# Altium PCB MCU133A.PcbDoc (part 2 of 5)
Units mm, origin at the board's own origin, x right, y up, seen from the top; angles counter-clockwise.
Board outline 58.42 x 139.7 mm, 4 copper layers (Top Signal, GND, PWR, Bottom Signal), stack 1.565 mm thick; 278 components, 226 nets, 1057 pads, 868 vias.
Unrouted connection lines stored in the file: 237.
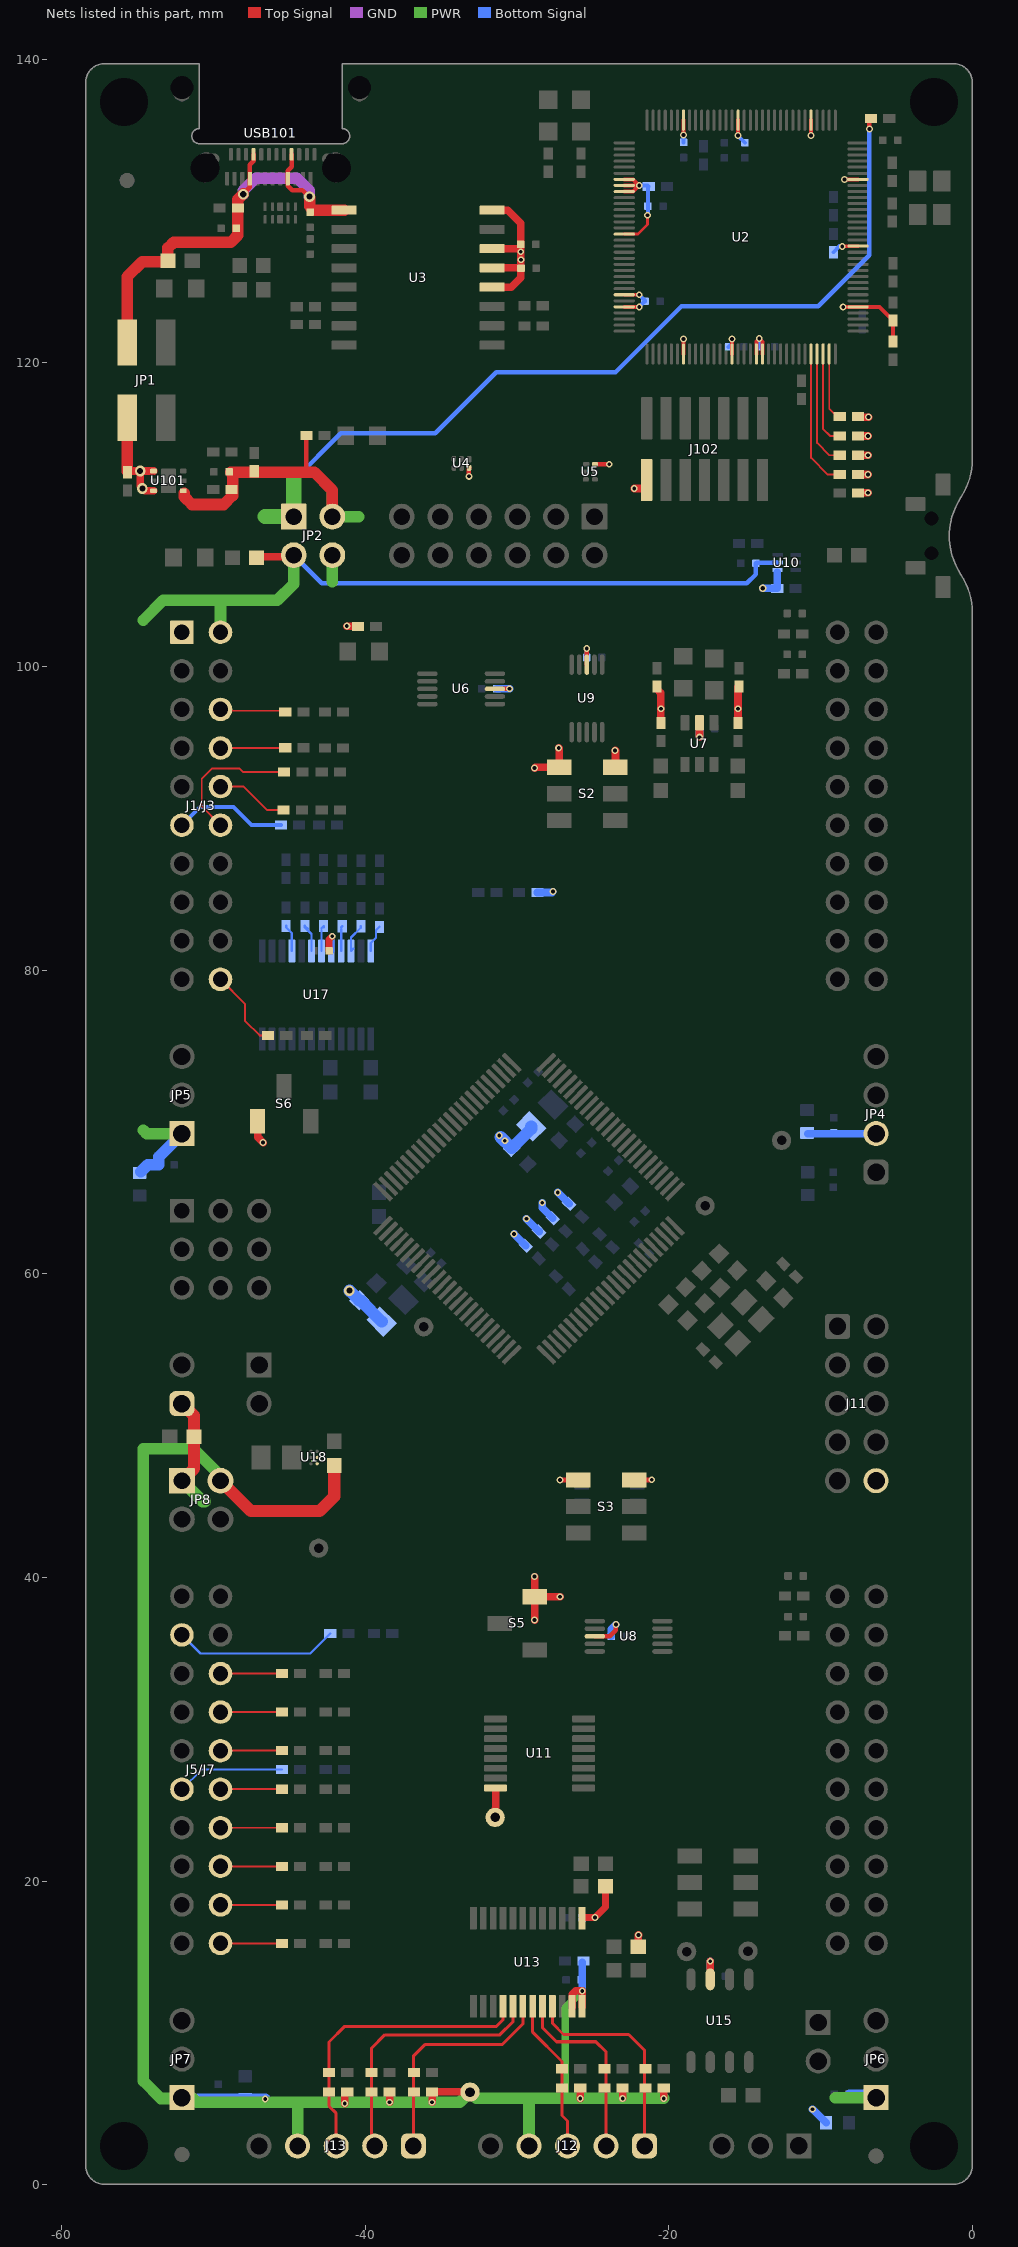
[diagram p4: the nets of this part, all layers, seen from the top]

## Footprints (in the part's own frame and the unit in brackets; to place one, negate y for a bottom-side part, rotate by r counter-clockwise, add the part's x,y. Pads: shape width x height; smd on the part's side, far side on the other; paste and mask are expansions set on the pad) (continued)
WURTH_61300211121#1 [mm] "Header, 2.54mm, 2x1, TH"
  rect 1.65x1.65 hole 1.15: 1(-1.27,0)
  round 1.65 hole 1.15: 2(1.27,0)
  silkscreen extent -2.54,-1.27 2.54,1.6, body extent -2.54,-1.27 2.54,1.27, height 8.54
WURTH_61300211121#2 [mm] "Header, 2.54mm, 2x1, TH"
  rrect50% 1.65x1.65 hole 1.15: 1(-1.27,0)
  round 1.65 hole 1.15: 2(1.27,0)
  body extent -2.54,-1.27 2.54,1.27, height 8.54
WURTH_61300311121 [mm] "Header, 2.54mm, 3x1, TH"
  rect 1.65x1.65 hole 1.15: 1(-2.54,0)
  round 1.65 hole 1.15: 2(0,0) 3(2.54,0)
  silkscreen extent -3.81,-1.65 3.81,1.27, body extent -3.81,-1.27 3.81,1.27, height 8.54
WURTH_61300411121 [mm] "Header, 2.54mm, 4x1, TH"
  rrect50% 1.65x1.65 hole 1.15: 1(-3.81,0)
  round 1.65 hole 1.15: 2(-1.27,0) 3(1.27,0) 4(3.81,0)
  body extent -5.08,-1.27 5.08,1.27, height 8.54
Wurth_61300511121 [mm] "Header, 2.54mm, 5x1, TH"
  rrect50% 1.65x1.65 hole 1.1: 1(-5.08,0)
  round 1.65 hole 1.1: 2(-2.54,0) 3(0,0) 4(2.54,0) 5(5.08,0)
  body extent -6.35,-1.27 6.35,1.27, height 8.54
WURTH_61301021121 [mm] "Header, 2.54mm, 5x2, TH"
  rrect25% 1.65x1.65 hole 1.15: 1(-5.08,-1.27)
  round 1.65 hole 1.15: 2(-5.08,1.27) 3(-2.54,-1.27) 4(-2.54,1.27) 5(0,-1.27) 6(0,1.27) 7(2.54,-1.27) 8(2.54,1.27) 9(5.08,-1.27) 10(5.08,1.27)
  silkscreen extent -6.35,-2.9 6.35,2.54, body extent -6.35,-2.54 6.35,2.54, height 8.54
YFF0006AEAE [mm] "DSBGA-6"
  round 0.23 smd paste-0.13 mask+0.038: A1(-0.2,0.4) A2(0.2,0.4) B1(-0.2,0) B2(0.2,0) C1(-0.2,-0.4) C2(0.2,-0.4)
  body extent -0.45,-0.65 0.45,0.65, height 0.63

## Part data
C1 C2 C10 C11 C12 C14 C20 C21 C22 C43 C44 C45 C46 C54 C55 C60 C64 C65 C66 C74 C81 C82 C83 C84 C105 C106: library part CMP-0090362-1, "0.1µF ±10% 10V Ceramic Capacitor X7R 0402 (1005 Metric)", Digikey Part Number=732-7513-1-ND, Manufacturer="Wurth Electronics", Mouser Part Number=710-885012205018, Operating Temperature Range="-55°C to +125°C", TempCo=15%, Temperature Characteristic=X7R, Tolerance_%=10%, ValueDisplayed=100000pF
C6 C7 C17: library part CMP-0006228-2, "CAP, CERM, 0.1 uF, 16 V, +/- 10%, X7R, 0402", Cap_Case=0402, Manufacturer="Wurth Elektronik", Supplier Part Number 1=732-7532-1-ND, TempCo=X7R, Tolerance_%=10%, Value1=Unknown, Value2=16V, ValueDisplayed=0.1uF
C9 C18 C19 C111 C113 C115 C117 C119: library part CMP-0092309-1, "Cap Ceramic 10uF 10V X5R 10% SMD 0603 85C Paper T/R", Digikey Part Number=311-1782-1-ND, Manufacturer=YAGEO, Mouser Part Number=603-CC603KRX5R6BB106, Octopart Part Number=1f0ad7d7c223c0cd, Operating Temperature Range="-55°C to +85°C", TempCo=15%, Temperature Characteristic=X5R, Tolerance_%=10%, ValueDisplayed=10uF
C15 C16 C24: library part CMP-0007091-1, "CAP, CERM, 2.2 uF, 10 V, +/- 10%, X5R, AEC-Q200 Grade 3, 0603", Cap_Case=0603, Manufacturer=TDK, Supplier Part Number 1=445-12444-1-ND, TempCo=X5R, Tolerance_%=10%, Value1=Unknown, Value2=10V, ValueDisplayed=2.2uF
C25 C26 C27 C28 C29 C30 C31 C32 C33 C34 C35 C36 C37 C38 C39 C40 C75 C76 C77 C78 C107 C108: library part CMP-0006456-2, "CAP, CERM, 330 pF, 50 V, +/- 5%, C0G/NP0, 0402", Cap_Case=0402, Manufacturer=MuRata, Supplier Part Number 1=490-1295-1-ND, TempCo=C0G/NP0, Tolerance_%=5%, Value1=Unknown, Value2=50V, ValueDisplayed=330pF
C41 C42: library part CMP-0006239-2, "CAP, CERM, 12 pF, 25 V, +/- 5%, C0G/NP0, AEC-Q200 Grade 1, 0402", Cap_Case=0402, Manufacturer=Kemet, Supplier Part Number 1=399-6829-1-ND, TempCo=C0G/NP0, Tolerance_%=5%, Value1=Unknown, Value2=25V, ValueDisplayed=12pF
C50 C51 C52 C53 C58 C102: library part CMP-0090363-1, "10000pF ±10% 25V Ceramic Capacitor X7R 0402 (1005 Metric)", Digikey Part Number=732-7545-1-ND, Manufacturer="Wurth Electronics", Mouser Part Number=710-885012205050, Operating Temperature Range="-55°C to +125°C", TempCo=15%, Temperature Characteristic=X7R, Tolerance_%=10%, ValueDisplayed=10000pF
C56 C57 C59 C61 C100 C103: library part CMP-0064924-2, "CAP, CERM, 1 uF, 10 V,+/- 20%, X5R, 0402", Cap_Case=0402, Manufacturer="Wurth Elektronik", Supplier Part Number 1=732-7489-1-ND, TempCo=X5R, Tolerance_%=20%, Value1=Unknown, Value2=10V, ValueDisplayed=1uF
C62 C63: library part CMP-0006345-2, "CAP, CERM, 12 pF, 50 V, +/- 5%, C0G/NP0, 0402", Cap_Case=0402, Manufacturer="Samsung Electro-Mechanics", Supplier Part Number 1=1276-1178-1-ND, TempCo=C0G/NP0, Tolerance_%=5%, Value1=Unknown, Value2=50V, ValueDisplayed=12pF
C67 C68 C69 C70 C71 C72 C73: library part CMP-0006231-2, "CAP, CERM, 1000 pF, 50 V, +/- 10%, X7R, 0402", Cap_Case=0402, Manufacturer="Wurth Elektronik", Supplier Part Number 1=732-7556-1-ND, TempCo=X7R, Tolerance_%=10%, Value1=Unknown, Value2=50V, ValueDisplayed=1000pF
C101: library part CMP-0092424-1, "Cap Cer 3300pF 50V X7R 0402", Digikey Part Number=732-7559-1-ND, Manufacturer="Wurth Electronics", Mouser Part Number=710-885012205064, Operating Temperature Range="-55°C to +125°C", TempCo=15%, Temperature Characteristic=X7R, Tolerance_%=10%, ValueDisplayed=3.3nF
C109: library part CMP-0006825-5, "CAP, CERM, 2.2 uF, 16 V, +/- 20%, X5R, 0603", Cap_Case=0603, Manufacturer="Wurth Elektronik", Supplier Part Number 1=732-7915-1-ND, TempCo=X5R, Tolerance_%=20%, Value1=Unknown, Value2=16V, ValueDisplayed=2.2uF
C110: library part CMP-0086225-1, "CAP, CERM, 10 µF, 16 V,+/- 10%, X5R, 0603", Cap_Case=0603, Manufacturer=MuRata, Supplier Part Number 1=490-10728-1-ND, TempCo=X5R, Tolerance_%=10%, Value2=16V, ValueDisplayed=10µF
C112 C114 C116 C118 C120 C121 C122: library part CMP-0090362-1, "0.1µF ±10% 10V Ceramic Capacitor X7R 0402 (1005 Metric)", Digikey Part Number=732-7513-1-ND, Manufacturer="Wurth Electronics", Mouser Part Number=710-885012205018, Operating Temperature Range="-55°C to +125°C", TempCo=15%, Temperature Characteristic=X7R, Tolerance_%=10%, ValueDisplayed=0.1uF
"CE Logo1": library part CMP-0074844-1
FID1 FID2 FID3 FID4 FID5 FID6: library part CMP-0077181-1, "Fiducial mark.  There is nothing to buy or mount.", Manufacturer=N/A
J1/J3: library part CMP-0003837-4, "Receptacle, 2.54mm, 10x2, Tin, TH", Alternate Manufacturer="Major League Electronics", Alternate PartNumber=CRD-081413-A-G, Manufacturer=Samtec, Supplier Part Number 1=SAM1204-10-ND
J4/J2: library part CMP-0078266-4, "Receptacle, 2.54mm, 10x2, Tin, TH", Alternate Manufacturer="Major League Electronics", Alternate PartNumber=CRD-081413-A-G, Manufacturer=Samtec, Supplier Part Number 1=SAM1204-10-ND
J5/J7: library part CMP-0081070-3, "Receptacle, 2.54mm, 10x2, Tin, TH", Alternate Manufacturer="Major League Electronics", Alternate PartNumber=CRD-081413-A-G, Manufacturer=Samtec, Supplier Part Number 1=SAM1204-10-ND
J8/J6: library part CMP-0081071-3, "Receptacle, 2.54mm, 10x2, Tin, TH", Alternate Manufacturer="Major League Electronics", Alternate PartNumber=CRD-081413-A-G, Manufacturer=Samtec, Supplier Part Number 1=SAM1204-10-ND
J10: library part CMP-0090263-1, Digikey Part Number=SAM10328-ND, Manufacturer=Samtec, Mouser Part Number=200-TSW10307GT, Operating Temperature Range="-55°C to +125°C"
J11: library part CMP-0054806-3, "Header, 2.54 mm, 5x2, Gold, TH", Current_A=3A, Manufacturer="Wurth Elektronik", Supplier Part Number 1=732-2672-ND, Voltage_V=250V
J12 J13: library part CMP-0084909-1, "Header, 2.54mm, 5x1, Gold, TH", Color=Black, Current_A=3A, Manufacturer="Wurth Elektronik", Voltage_V=250V
J14 JP5 JP6 JP7: library part CMP-0054796-1, "Header, 2.54 mm, 3x1, Gold, TH", Manufacturer="Wurth Elektronik", Supplier Part Number 1=732-5316-ND
J15 JP9: library part CMP-0054794-1, "Header, 2.54 mm, 2x1, Gold, TH", Manufacturer="Wurth Elektronik", Supplier Part Number 1=732-5315-ND
J16: library part CMP-0054794-2, "Header, 2.54 mm, 2x1, Gold, TH", Color=Black, Manufacturer="Wurth Elektronik", Supplier Part Number 1=732-5315-ND
J101: library part CMP-0092423-1, "THT Vertical Pin Header WR-PHD, Pitch 2.54 mm, Dual Row, 12 pins", Current_A=3A, Digikey Part Number=732-5297-ND, Manufacturer="Wurth Electronics", Mouser Part Number=710-61301221121, Operating Temperature Range="-40°C to +105°C", Voltage_V=250V
J102: library part CMP-0092335-1, "Connector, Header, Dual Row, 14 pin, .05\" pitch/row spacing, Male, Shrouded, Keyed, IDC, SMT", Current_A=3.4A, Digikey Part Number=612-FTSH-107-01-F-DV-K-ND, Manufacturer=Samtec, Mouser Part Number=200-FTSH10701FDVK, Octopart Part Number=b9dd70752dfc661a, Operating Temperature Range="-55°C to +125°C"
JP1: library part CMP-0055559-1, "Header, 2.54mm, 2x2, Gold, SMT", Color=Black, Manufacturer=Samtec, Supplier Part Number 1=TSM-102-01-L-DV-ND, Voltage_V=475V
JP2 JP8: library part CMP-0092422-1, "THT Vertical Pin Header WR-PHD, Pitch 2.54 mm, Dual Row, 4 pins", Current_A=3A, Digikey Part Number=732-5294-ND, Manufacturer="Wurth Electronics", Mouser Part Number=710-61300421121, Operating Temperature Range="-40°C to +105°C", Voltage_V=250V
JP4: library part CMP-0054798-2, "Header, 2.54 mm, 4x1, Gold, TH", Color=Black, Manufacturer="Wurth Elektronik", Supplier Part Number 1=732-5317-ND
L2: library part CMP-0003093-1, "Ferrite Bead, 60 ohm @ 100 MHz, 3 A, 0805", Manufacturer="Wurth Elektronik", Supplier Part Number 1=732-1612-1-ND, Value1="0.025 ohm", Value2=3A, ValueDisplayed="60 ohm"
L3: library part CMP-0003073-1, "Ferrite Bead, 220 ohm @ 100 MHz, 2 A, 0805", Manufacturer="Wurth Elektronik", Supplier Part Number 1=732-1614-1-ND, Value1="0.05 ohm", Value2=2A, ValueDisplayed="220 ohm"
L4: library part CMP-0058739-1, "Inductor, Multilayer, Ferrite, 1 uH, 0.8 A, 0.19 ohm, SMD", Manufacturer=MuRata, Supplier Part Number 1=490-4992-1-ND, Value1="0.19 ohm", Value2=0.8A, ValueDisplayed=1uH
LED0 LED1 LED4 LED6 LED7: library part CMP-0002951-3, "LED, Red, SMD", Color=Red, Manufacturer="Wurth Elektronik", Power_TotalModule=72mW, Value1=0.072W, Value2=1.9V
LED2 LED3: library part CMP-0002889-2, "LED, Blue, SMD", Color=Blue, Manufacturer=Lite-On, Value1=W, Value2=3.3V
LED5: library part CMP-0002830-3, "LED, Green, SMD", Color=green, Manufacturer=Lite-On, Value1=W, Value2=2.1V
Logo1 Logo5: library part CMP-0074838-1, "Texas Instrument Corporate Signature"
Logo3: library part CMP-0074847-1, "FCC_disclaimer"
Logo4: library part CMP-0074769-1
M1 M2 M3 M4 M5 M6 M7 M8 M9 M10 M11 M12 M13: library part CMP-0003761-2, "Shunt, 2.54mm, Gold, Black", Manufacturer="Wurth Elektronik", Supplier Part Number 1=732-2678-ND
MH1 MH2 MH3 MH4: library part CMP-0078424-2, "PCB Mounting Hole, No Pad", Manufacturer=Any, PartNumber=N/A
R1 R2 R8 R9 R12 R13 R14 R15 R16 R17 R18 R19 R20 R21 R22 R23 R24 R25 R26 R27 R44 R45 R49 R50 R84 R85 R86 R87 R103 R104 R109 R110: library part CMP-0027004-2, "RES, 0, 5%, 0.063 W, 0402", Manufacturer="Yageo America", Power_W=63mW, Supplier Part Number 1=311-0.0JRCT-ND, TempCo="200 ppm/C", Tolerance_%=5%, Value2=0.063W, Value_Code=0000, ValueDisplayed=0
R3 R28 R29 R105: library part CMP-0026962-3, "RES, 680, 5%, 0.063 W, AEC-Q200 Grade 0, 0402", Manufacturer=Vishay-Dale, Power_W=63mW, Supplier Part Number 1=541-680JCT-ND, TempCo="200 ppm/C", Tolerance_%=5%, Value2=0.063W, Value_Code=680R, ValueDisplayed=680
R5: library part CMP-0025874-4, "RES, 0, 5%, 0.1 W, AEC-Q200 Grade 0, 0603", Manufacturer=Panasonic, Power_W=100mW, Supplier Part Number 1=P0.0GCT-ND, TempCo="600 ppm/C", Tolerance_%=5%, Value2=0.1W, Value_Code=0000, ValueDisplayed=0
R7 R43: library part CMP-0025921-5, "RES, 3.0 k, 5%, 0.1 W, 0603", Manufacturer=Yageo, Power_W=100mW, Supplier Part Number 1=311-3.0KGRCT-ND, TempCo="100 ppm/C", Tolerance_%=5%, Value2=0.1W, Value_Code=3k00, ValueDisplayed=3.0k
R10 R11: library part CMP-0026890-5, "RES, 2.2 k, 5%, 0.063 W, AEC-Q200 Grade 0, 0402", Manufacturer=Vishay-Dale, Power_W=63mW, Supplier Part Number 1=541-2.2KJCT-ND, TempCo="200 ppm/C", Tolerance_%=5%, Value2=0.063W, Value_Code=2k20, ValueDisplayed=2.2k
R30 R31: library part CMP-0026826-2, "RES, 10 M, 5%, 0.063 W, AEC-Q200 Grade 0, 0402", Manufacturer=Vishay-Dale, Power_W=63mW, Supplier Part Number 1=541-10MJCT-ND, TempCo="200 ppm/C", Tolerance_%=5%, Value2=0.063W, Value_Code=10M0, ValueDisplayed=10M
R32 R33 R34 R35 R36 R37 R47 R52 R53 R107 R108: library part CMP-0025697-4, "RES, 0, 5%, 0.1 W, AEC-Q200 Grade 0, 0603", Manufacturer=Vishay-Dale, Power_W=100mW, Supplier Part Number 1=541-0.0GCT-ND, TempCo="200 ppm/C", Tolerance_%=5%, Value2=0.1W, Value_Code=0000, ValueDisplayed=0
R38 R39: library part CMP-0022746-5, "RES, 10.0 k, 1%, 0.1 W, 0603", Manufacturer=Yageo, Power_W=100mW, Supplier Part Number 1=311-10.0KHRCT-ND, TempCo="100 ppm/C", Tolerance_%=1%, Value2=0.1W, Value_Code=10k0, ValueDisplayed=10.0k
R48: library part CMP-0025769-4, "RES, 2.2 k, 5%, 0.1 W, AEC-Q200 Grade 0, 0603", Manufacturer=Vishay-Dale, Power_W=100mW, Supplier Part Number 1=541-2.2KGCT-ND, TempCo="200 ppm/C", Tolerance_%=5%, Value2=0.1W, Value_Code=2k20, ValueDisplayed=2.2k
R57: library part CMP-0026918-5, "RES, 3.3 k, 5%, 0.063 W, AEC-Q200 Grade 0, 0402", Manufacturer=Vishay-Dale, Power_W=63mW, Supplier Part Number 1=541-3.3KJCT-ND, TempCo="200 ppm/C", Tolerance_%=5%, Value2=0.063W, Value_Code=3k30, ValueDisplayed=3.3k
R58 R59 R60 R61 R72 R73 R74 R75 R76 R77: library part CMP-0026071-3, "RES, 1.00 k, 1%, 0.063 W, AEC-Q200 Grade 0, 0402", Manufacturer=Vishay-Dale, Power_W=63mW, Supplier Part Number 1=541-1.00KLCT-ND, TempCo="100 ppm/C", Tolerance_%=1%, Value2=0.063W, Value_Code=1k00, ValueDisplayed=1.00k
R62: library part CMP-0026824-3, "RES, 100, 5%, 0.063 W, AEC-Q200 Grade 0, 0402", Manufacturer=Vishay-Dale, Power_W=63mW, Supplier Part Number 1=541-100JCT-ND, TempCo="200 ppm/C", Tolerance_%=5%, Value2=0.063W, Value_Code=100R, ValueDisplayed=100
R63 R64: library part CMP-0026736-1, "RES, 470, 1%, 0.063 W, 0402", Manufacturer="Yageo America", Power_W=63mW, Supplier Part Number 1=311-470LRCT-ND, TempCo="100 ppm/C", Tolerance_%=1%, Value2=0.063W, Value_Code=470R, ValueDisplayed=470
R65 R67: library part CMP-0026825-5, "RES, 10 k, 5%, 0.063 W, AEC-Q200 Grade 0, 0402", Manufacturer=Vishay-Dale, Power_W=63mW, Supplier Part Number 1=541-10KJCT-ND, TempCo="200 ppm/C", Tolerance_%=5%, Value2=0.063W, Value_Code=10k0, ValueDisplayed=10k
R68: library part CMP-0026413-2, "RES, 4.87 k, 1%, 0.063 W, AEC-Q200 Grade 0, 0402", Manufacturer=Vishay-Dale, Power_W=63mW, Supplier Part Number 1=541-4.87KLCT-ND, TempCo="100 ppm/C", Tolerance_%=1%, Value2=0.063W, Value_Code=4k87, ValueDisplayed=4.87k
R70: library part CMP-0026946-3, "RES, 51, 5%, 0.063 W, AEC-Q200 Grade 0, 0402", Manufacturer=Vishay-Dale, Power_W=63mW, Supplier Part Number 1=541-51JCT-ND, TempCo="200 ppm/C", Tolerance_%=5%, Value2=0.063W, Value_Code=51R0, ValueDisplayed=51
R79: library part CMP-0022769-3, "RES, 120, 1%, 0.1 W, 0603", Manufacturer="Yageo America", Power_W=100mW, Supplier Part Number 1=311-120HRCT-ND, TempCo="200 ppm/C", Tolerance_%=1%, Value2=0.1W, Value_Code=120R
R82 R83: library part CMP-0026992-3, "RES, 0, 5%, 0.1 W, AEC-Q200 Grade 0, 0402", Manufacturer=Panasonic, Power_W=100mW, Supplier Part Number 1=P0.0JCT-ND, TempCo="600 ppm/C", Tolerance_%=5%, Value2=0.1W, Value_Code=0000, ValueDisplayed=0
R88 R89: library part CMP-0025932-5, "RES, 5.1 k, 5%, 0.1 W, 0603", Manufacturer=Yageo, Power_W=100mW, Supplier Part Number 1=311-5.1KGRCT-ND, TempCo="100 ppm/C", Tolerance_%=5%, Value2=0.1W, Value_Code=5k10, ValueDisplayed=5.1k
R100: library part CMP-0026100-2, "RES, 1.00 M, 1%, 0.063 W, AEC-Q200 Grade 0, 0402", Manufacturer=Vishay-Dale, Power_W=63mW, Supplier Part Number 1=541-1.00MLCT-ND, TempCo="100 ppm/C", Tolerance_%=1%, Value2=0.063W, Value_Code=1M00, ValueDisplayed=1.00M
R101: library part CMP-0026441-2, "RES, 52.3 k, 1%, 0.063 W, AEC-Q200 Grade 0, 0402", Manufacturer=Vishay-Dale, Power_W=63mW, Supplier Part Number 1=541-52.3KLCT-ND, TempCo="100 ppm/C", Tolerance_%=1%, Value2=0.063W, Value_Code=52k3, ValueDisplayed=52.3k
R102: library part CMP-0078244-2, "RES, 30.0 k, 1%, 0.063 W, AEC-Q200 Grade 0, 0402", Manufacturer=Vishay-Dale, Power_W=63mW, Supplier Part Number 1=541-30.0KLCT-ND, TempCo="100 ppm/C", Tolerance_%=1%, Value2=0.063W, Value_Code=30k0, ValueDisplayed=30.0k
R106: library part CMP-0023387-3, "RES, 50, 0.1%, 0.125 W, 0603", Manufacturer="Vishay Thin Film", Power_W=125mW, Supplier Part Number 1=FC0603-50BFCT-ND, TempCo="25 ppm/C", Tolerance_%=0.1%, Value2=0.125W, Value_Code=50R0, ValueDisplayed=50
R111 R112: library part CMP-0027004-2, "RES, 0, 5%, 0.063 W, 0402", Manufacturer="Yageo America", Power_W=63mW, Supplier Part Number 1=311-0.0JRCT-ND, TempCo="200 ppm/C", Tolerance_%=5%, Value2=0.063W, Value_Code=0000, ValueDisplayed=10k
S1: library part CMP-0002328-1, "Switch, SPST, 0.05 A, 12 VDC, SMD", CurrentRating_mA=50A, Manufacturer=Diptronics
S2 S3: library part CMP-0002233-1, "Switch, Dual SPDT,  2 Pos, 0.1A, 6VDC, SMD", CurrentRating_mA=100A, Manufacturer="Copal Electronics", Supplier Part Number 1=CASD20JCT-ND
S4: library part CMP-0002123-2, "SLIDE SWITCH DPDT  .1A, SMT", CurrentRating_mA=100A, Manufacturer="Copal Electronics", Supplier Part Number 1=CAS220JCT-ND
S5 S6: library part CMP-0002139-2, "Switch, Slide, SPDT  100mA, SMT", CurrentRating_mA=100A, Manufacturer="Copal Electronics", Supplier Part Number 1=CAS120JCT-ND
TP1 TP2 TP3 TP4 TP5 TP6 TP7 TP8: library part CMP-0078143-3, "TEST POINT.  No entry in BOM.", Manufacturer=N/A
U1: library part CMP-0043282-2, "Real-Time Microcontroller, LQFP100", Frequency_Fixed=150MHz, Manufacturer="Texas Instruments", Max Supply Voltage=3.63V, Min Supply Voltage=2.8V, Operating Temperature Range="-40°C to +150°C"
U2: library part CMP-0077953-1, "MSP432E401YTPDT, PDT0128A (TQFP-128)", Alternate Manufacturer="Texas Instruments", Alternate PartNumber=MSP432E401YTPDTR
U3: library part CMP-0091303-1, "Full/Low Speed Isolated USB Repeater, SOIC16-Wide", Manufacturer="Texas Instruments", Max Supply Voltage=5.5V, Min Supply Voltage=3V, Nominal Supply Current=9-9.5mA, Operating Temperature Range="-55°C to +150°C"
U4 U5: library part CMP-0043115-3, "4-Channel ESD Protection Array for High-Speed Data Interfaces, DRY0006A (USON-6)", Breakdown Voltage(Min)(V)=6, IO Capacitance(Typ)(pF)=1.6, IO Leakage Current(nA)=1, Manufacturer="Texas Instruments", Operating Temperature Range="-40 to 85 C", Rating=Catalog
U6 U8 U9: library part CMP-0067418-1, "DUAL 10-Ohm SPDT ANALOG SWITCH, DGS0010A (VSSOP-10)", Alternate Manufacturer="Texas Instruments", Alternate PartNumber=TS5A23157DGST
U7: library part CMP-0051789-2, "Dual Buffer/Driver with Open-Drain Output, DBV0006A, LARGE T&R", F @ Nom Voltage(Max)(Mhz)=150, Generic Part Number=SN74LVC2G07, ICC @ Nom Voltage(Max)(mA)=0.01, Manufacturer="Texas Instruments", Operating Temperature Range(C)="-40 to 125", Rating=Catalog, tpd @ Nom Voltage(Max)(ns)=8.6,4.4,3.7,2.9, Voltage(Nom)(V)=1.8,2.5,3.3,5
U10: library part CMP-0750051-1, "Overvoltage and Undervoltage Reset IC With Time Delay and Manual Reset, DSE0006A (WSON-6)", Alternate Manufacturer="Texas Instruments"
U11: library part CMP-0089841-1, "3 Circuit IC Switch 2:1 75Ohm 16-TSSOP", Digikey Part Number=296-3833-1-ND, Manufacturer="Texas Instruments", Max Supply Voltage=5.5V, Min Supply Voltage=2V, Mouser Part Number=595-SN74LV4053APWR, Nominal Supply Current=20uA, On State Resistance=100-225Ω, Operating Temperature Range="-40°C to +85°C"
U13: library part CMP-0121414-1, "8-Bit Dual-Supply Bus Transceiver With Configurable Voltage Translation and 3-State Outputs", Digikey Part Number=296-34079-5-ND, Manufacturer="Texas Instruments", Mouser Part Number=595-SN74LVC8T245PWR, Nominal Supply Current=25uA, Operating Temperature Range="-40°C to +85°C"
U15: library part CMP-0080978-2, "3.3-V CAN Transceivers with CAN FD (Flexible Data Rate), D0008A (SOIC-8)", Alternate Manufacturer="Texas Instruments", Alternate PartNumber=TCAN332GD
U16: library part CMP-0073613-3, "4-Channel Ultra-Low-Capacitance IEC ESD Protection Diode, DQA0010A (USON-10)", Alternate Manufacturer="Texas Instruments"
U17: library part CMP-0092155-1, "3.3-V, 2:1 (SPDT), 6-channel analog multiplexer with 1.8-V compatible control inputs 24-TSSOP -40 to 85", Digikey Part Number=296-24570-1-ND, Manufacturer="Texas Instruments", Max Supply Voltage=3.6V, Min Supply Voltage=1.65V, Mouser Part Number=595-TS3A27518EPWR, Nominal Supply Current=0.01-0.04uA, Octopart Part Number=cf0206a9c1b910c5, On State Resistance=4.4Ω, Operating Temperature Range="-40°C to +85°C"
U18: library part CMP-0067212-2, "5V, 500mA, 4MHz Step-Up DC/DC Converter, YFF0006AEAE (DSBGA-6)", Alternate Manufacturer="Texas Instruments", Alternate PartNumber=TPS61241YFFT, Operating Temperature Range="-40 to 85 C", Rating=Catalog
U101: library part CMP-0066914-5, "1% High-Accuracy, 1-A, Low-Dropout Regulator with Reverse Current Protection, DRV0006A (WSON-6)", Alternate Manufacturer="Texas Instruments", Alternate PartNumber=TPS7A3701DRVT
USB101: library part CMP-0092137-1, "Connector, USB Type-C 24 pin Mid Mount dual row Receptacle Surface Mount", Manufacturer=MUP, Operating Temperature Range="-25°C to +85°C"
Y1: library part CMP-0094478-1, "Crystal 16 MHz ±20ppm Crystal 8pF 70 Ohms 4-SMD, No Lead", Digikey Part Number=732-830064296CT-ND, Frequency Stability=20ppm, Frequency_Fixed=16MHz, Load Capacitance=8pF, Manufacturer=Wurth, Mouser Part Number=710-830064296, Operating Temperature Range="-10°C to +70°C"
Y2: library part CMP-0093781-1, "20 MHz ±10ppm Crystal 8pF 50 Ohms 4-SMD, No Lead", Digikey Part Number=1923-830108207209CT-ND, Frequency Stability=20ppm, Frequency Tolerance=10ppm, Frequency_Fixed=20MHz, Load Capacitance=8pF, Manufacturer="Wurth Electronics", Mouser Part Number=710-830108207209, Operating Temperature Range="-40°C to +85°C"
ZZ1: library part CMP-0077236-1
ZZ2: library part CMP-0077237-1
ZZ3: library part CMP-0077238-1

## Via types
v1: diameter 0.45, hole 0.25, Top Signal to Bottom Signal, tented both sides, 822 vias
v2: diameter 0.5, hole 0.3, Top Signal to Bottom Signal, tented both sides, 22 vias
v3: diameter 0.7, hole 0.4, Top Signal to Bottom Signal, tented both sides, 17 vias
v4: diameter 0.4, hole 0.2, Top Signal to Bottom Signal, tented both sides, 5 vias
v5: diameter 0.5, hole 0.2, Top Signal to Bottom Signal, tented both sides, 2 vias

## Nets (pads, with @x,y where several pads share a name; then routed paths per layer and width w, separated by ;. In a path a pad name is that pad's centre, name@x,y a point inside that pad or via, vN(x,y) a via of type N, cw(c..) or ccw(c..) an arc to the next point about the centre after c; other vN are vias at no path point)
+3V3_MCU: C6.1 C16.1 C18.2 C43.1 C44.2 C45.1 C46.2 C64.1 C74.1 C109.1 C113.2 C114.1 C117.2 C118.1 C121.1 J1/J3.1 J11.10 J16.1 JP2.4 JP4.2 JP6.1 JP8.1 L2.1 L3.1 R3.2 R10.2 R11.2 R28.2 R29.2 R30.2 R31.2 R47.2 R48.2 R82.1 R111.2 R112.2 S2.1 S2.4 S3.3 S3.6 S5.3 S6.1 TP4.1 U6.8 U7.5 U8.8 U9.8 U10.1 U11.16 U13.1 U15.3 U17.8 | length 70.2
  Top Signal w0.3: U6.8@-31.454,98.523 -31.442,98.535 v1(-30.489,98.535) ; v1(-27.164,46.416) S3.6@-25.974,46.416 ; U9.8@-25.41,100.239 v1(-25.41,101.192) ; U9.8@-25.398,100.124 -25.398,100.824 ; U8.8@-24.87,36.121 -23.887,36.121 -23.488,36.519 v1(-23.488,36.888) ; S3.3@-22.274,46.416 -21.138,46.416 v1(-21.126,46.428)
  Top Signal w0.45: C121.1@-42.381,81.263 -42.381,82.018 v1(-42.165,82.234) ; U13.1@-25.719,17.602 v1(-24.864,17.602) -24.179,18.287 R47.2@-24.179,19.667
  Top Signal w0.5: S6.1@-47.09,70.053 -47.09,69.008 v1(-46.723,68.642) ; JP2.4@-42.165,107.329 JP2.4@-42.133,107.297 ; v1(-41.209,102.656) R3.2@-40.624,102.656 ; TP4.1@-31.421,24.774 -31.413,24.782 U11.16@-31.413,25.93 ; v1(-28.842,93.308) -28.791,93.359 S2.1@-27.229,93.359 ; v1(-28.84,37.193) S5.3@-28.84,38.722 ; v1@-28.84,40.045 S5.3@-28.84,38.722 ; v1(-27.257,94.629) -27.224,94.596 S2.1@-27.224,93.365 ; v1@-27.158,38.722 S5.3@-28.84,38.722 ; v1(-23.54,94.473) -23.512,94.445 S2.4@-23.512,93.377 ; R48.2@-22.017,15.659 -22.017,16.428 v1(-21.999,16.446) ; R28.2@-20.809,98.537 -20.523,98.251 R30.2@-20.523,96.284 ; v1(-17.983,95.344) U7.5@-17.983,96.297 ; U15.3@-17.276,13.529 U15.3@-17.273,13.526 ; U15.3@-17.27,13.535 v1(-17.27,14.712) ; R31.2@-15.443,96.284 R29.2@-15.443,98.646
  Top Signal w0.8: JP8.1@-52.071,46.369 -51.275,47.165 C109.1@-51.275,49.254 -51.275,50.653 J16.1@-52.071,51.449
  PWR w0.762: -42.165,105.594 JP2.4@-42.165,107.329 ; -9.04,5.729 JP6.1@-6.351,5.729
  PWR w0.8: JP8.1@-52.071,46.369 -50.697,44.995 -50.568,44.995
  Bottom Signal w0.254: U17.8@-42.259,81.291 U17.8@-42.231,81.263 ; v1@-42.165,82.229 v1(-42.165,82.234)
  Bottom Signal w0.3: v1(-25.41,101.192) -25.407,101.189 C46.2@-25.407,100.591
  Bottom Signal w0.45: U17.8@-42.231,81.263 -42.231,82.163 v1@-42.165,82.229 ; C64.1@-25.7,17.578 -24.888,17.578 v1(-24.864,17.602)
  Bottom Signal w0.5: C43.1@-31.336,98.535 v1(-30.489,98.535) ; v1(-30.192,62.622) -30.192,62.618 R112.2@-29.421,61.847 ; v1(-29.383,63.618) R10.2@-28.547,62.781 ; R11.2@-28.66,85.114 -27.697,85.114 v1(-27.639,85.172) ; v1(-28.333,64.672) -28.333,64.337 R111.2@-27.647,63.65 ; v1(-27.321,65.359) -27.318,65.359 R82.1@-26.568,64.608 ; C45.1@-23.786,36.121 -23.786,36.591 v1(-23.488,36.888) ; v1(-17.983,95.344) C44.2@-17.983,95.879 ; v1(-17.27,14.712) -17.265,14.706 C74.1@-17.265,13.738 ; v2(-13.825,105.145) C6.1@-12.862,105.145 ; C6.1@-12.856,105.15 -12.856,106.211 ; C113.2@-10.848,69.229 JP4.2@-6.351,69.229 JP4.2@-6.478,69.102 ; v1(-10.541,4.972) -10.535,4.972 C117.2@-9.641,4.078
  Bottom Signal w0.6: C118.1@-8.111,5.958 -6.58,5.958 JP6.1@-6.351,5.729
  Bottom Signal w0.8: v3@-41.024,58.883 C16.1@-40.39,58.249 -40.316,58.249 L2.1@-38.911,56.845 ; v1@-31.081,69.011 C18.2@-30.344,68.274 -29.066,69.553 L3.1@-29.066,69.704
  other v1: -27.164,38.722 -28.85,40.065 -30.802,68.762 -31.174,69.105 -20.526,97.217 -15.446,97.217
  other v3: -41.047,58.891
+3V3_XDS110: C1.2 C2.2 C51.2 C52.2 C53.2 C54.2 C55.2 C56.1 C57.1 C58.2 C102.2 C103.1 J102.1 JP2.3 R57.2 R58.2 R59.2 R60.2 R61.2 R65.2 R70.2 R101.2 R105.2 U2.7 U2.8 U2.9 U2.16 U2.26 U2.28 U2.39 U2.47 U2.51 U2.52 U2.69 U2.79 U2.90 U2.101 U2.113 U2.122 U3.12 U3.13 U3.14 U3.16 U4.6 U5.6 U101.1 | length 66.7
  Top Signal w0.2: U2.16@-22.936,128.484 -22.036,128.484 -21.403,129.117 v1(-21.403,129.723)
  Top Signal w0.254: U2.28@-22.936,123.684 v1(-21.954,123.684) ; U2.26@-22.936,124.484 v1(-21.954,124.484) ; U2.9@-22.936,131.284 -22.354,131.284 v1(-21.954,131.684) ; U2.8@-22.936,131.684 v1(-21.954,131.684) ; U2.7@-22.936,132.084 -22.354,132.084 v1(-21.954,131.684) ; U2.39@-19.036,120.584 v1(-19.036,121.566) ; v1(-19.036,135.002) U2.122@-19.036,135.984 ; U2.47@-15.836,120.584 v1(-15.836,121.566) ; v1(-15.436,134.97) U2.113@-15.436,135.984 ; U2.51@-14.236,120.584 -14.236,121.401 v1(-14.042,121.595) -13.836,121.389 U2.52@-13.836,120.584 ; v1(-10.636,134.97) U2.101@-10.636,135.984 ; v1@-8.553,127.677 U2.79@-7.53,127.677 ; v1(-8.518,123.684) U2.69@-7.536,123.684 -6.133,123.684 R65.2@-5.233,122.784 ; v1(-8.427,132.084) U2.90@-7.536,132.084 ; R70.2@-5.242,121.406 -5.242,122.775 R65.2@-5.233,122.784 ; R65.2@-5.165,122.852 R65.2@-5.233,122.784
  Top Signal w0.3: -43.873,112.923 R105.2@-43.873,115.203 ; v1(-33.166,112.523) -33.166,113.067 U4.6@-33.154,113.079 ; U5.6@-24.87,113.32 v1(-23.928,113.32)
  Top Signal w0.5: U3.12@-31.64,124.982 -30.367,124.982 -29.755,125.594 C2.2@-29.755,126.252 ; U3.13@-31.64,126.252 C2.2@-29.755,126.252 ; U3.14@-31.64,127.522 v1@-29.84,127.522 ; U3.16@-31.64,130.062 -30.615,130.062 -29.755,129.202 -29.755,127.543 -29.755,126.928 C2.2@-29.755,126.252 ; C2.2@-29.736,126.236 -29.752,126.252 C2.2@-29.755,126.252 ; v1(-22.274,111.721) -21.64,111.721 -21.459,111.902 J102.1@-21.459,112.279
  Top Signal w0.508: R57.2@-7.547,111.442 R57.2@-7.543,111.438 v1(-6.878,111.438) ; R61.2@-7.547,112.642 v1(-6.882,112.642) ; R60.2@-7.547,113.912 v1(-6.882,113.912) ; R59.2@-7.547,115.182 v1(-6.882,115.182) ; R58.2@-7.518,116.423 v1(-6.853,116.423)
  Top Signal w0.762: -51.927,111.415 -51.927,111.187 -51.409,110.669 -49.325,110.669 -48.738,111.256 C102.2@-48.738,112.792 ; C102.2@-48.844,112.806 -43.358,112.806 -42.165,111.613 JP2.3@-42.165,109.869
  PWR w0.762: JP2.3@-42.165,109.508 JP2.3@-42.165,109.869 ; -42.165,111.446 JP2.3@-42.165,109.869 ; -40.435,109.869 JP2.3@-42.165,109.869
  Bottom Signal w0.254: v1(-21.954,123.684) -21.593,124.045 C55.2@-21.572,124.045 -21.572,124.102 v1(-21.954,124.484) ; v1(-21.954,131.684) -21.39,131.684 C57.1@-21.328,131.622 -21.37,131.58 -21.37,130.572 -21.37,129.708 -21.385,129.723 v1(-21.403,129.723) ; v1(-19.036,135.002) -19.036,134.527 C52.2@-19.031,134.522 ; C54.2@-16.062,121.052 -15.836,121.278 v1(-15.836,121.566) ; v1(-15.436,134.97) -15.436,134.948 C51.2@-14.987,134.499 ; C56.1@-9.165,127.281 -8.762,127.684 -8.739,127.661 v1(-8.582,127.661)
  Bottom Signal w0.3: C53.2@-14.083,121.052 -14.042,121.093 v1(-14.042,121.595)
  other v1: -29.744,126.785 -29.752,127.319
+5V0_MCU: C65.2 C67.1 C110.1 C115.2 C116.1 C119.2 C120.1 C122.1 J1/J3.21 J12.4 J13.4 JP2.2 JP5.1 JP7.1 JP8.2 R43.2 R72.2 R73.2 R74.2 R75.2 R76.2 R77.2 TP5.1 U10.2 U13.23 U13.24 U18.B2 U18.C2 | length 181.7
  Top Signal w0.305: U13.24@-25.719,11.702 U13.24@-25.708,11.713
  Top Signal w0.5: R43.2@-47.15,107.221 -44.813,107.221 JP2.2@-44.705,107.329 ; v1(-41.344,5.35) R77.2@-41.344,6.029 ; v1(-38.39,5.431) R76.2@-38.39,6.11 ; v1(-35.596,5.431) R75.2@-35.596,6.11 -33.107,6.11 TP5.1@-33.097,6.1 ; U13.23@-26.366,11.702 -26.366,12.539 -26.143,12.762 v1(-25.708,12.762) U13.24@-25.708,11.713 ; R74.2@-25.836,6.364 -25.83,6.358 v1(-25.83,5.679) ; v1(-23.042,5.685) R73.2@-23.042,6.364 ; v1(-20.331,5.685) R72.2@-20.331,6.364
  Top Signal w0.8: JP8.2@-49.531,46.369 -47.524,44.362 -43.007,44.362 -42.037,45.332 C110.1@-42.037,47.365
  PWR w0.5: -26.816,5.685 -26.816,11.654 v1(-25.708,12.762)
  PWR w0.762: -54.607,69.451 -54.385,69.229 JP5.1@-52.071,69.229 ; -54.607,103.058 -53.314,104.351 -49.502,104.351 ; JP7.1@-52.071,5.679 -53.458,5.679 -54.607,6.828 -54.607,48.464 -51.308,48.464 -49.531,46.687 JP8.2@-49.531,46.369 ; JP7.1@-52.071,5.729 -51.381,5.729 -51.083,5.431 -44.529,5.431 ; J1/J3.21@-49.531,102.249 -49.531,104.322 -49.502,104.351 ; JP2.2@-44.705,107.329 -44.705,105.432 -45.786,104.351 -49.502,104.351 ; J13.4@-44.451,2.554 -44.451,5.353 -44.529,5.431 ; J12.4@-29.211,2.554 -29.211,5.62 -29.276,5.685 ; v1(-20.331,5.685) v1(-23.042,5.685) -26.816,5.685 -29.276,5.685 ; -44.529,5.431 v1(-38.39,5.431) v1(-35.596,5.431) -33.766,5.431 TP5.1@-33.097,6.1 -32.682,5.685 -29.276,5.685
  Bottom Signal w0.3: JP2.2@-44.705,107.329 -42.851,105.475 -14.874,105.475 -14.263,106.086 C122.1@-14.263,106.796 -14.212,106.846 U10.2@-12.836,106.846
  Bottom Signal w0.305: C67.1@-25.708,14.646 C67.1@-25.629,14.725
  Bottom Signal w0.5: v1(-25.708,12.762) C67.1@-25.708,14.646
  Bottom Signal w0.762: C115.2@-54.776,66.72 -54.324,67.172 C116.1@-53.587,67.172 -53.587,67.713 JP5.1@-52.071,69.229 ; JP7.1@-51.952,5.61 C120.1@-49.683,5.61 ; C120.1@-49.654,5.639 C119.2@-47.905,5.639 v1(-46.585,5.639)
+5V0_USB: C101.2 C105.2 JP1.1 R7.2 R100.2 U3.1 USB101.A4 USB101.A9 USB101.B4 USB101.B9 | length 31.6
  Top Signal w0.3: v3@-48.021,131.135 -47.596,131.56 USB101.A9@-47.596,132.134 -47.596,133.054 -47.346,133.304 USB101.B4@-47.346,133.734 ; USB101.B9@-44.846,133.734 -44.846,132.903 -45.096,132.653 USB101.A4@-45.096,132.134 -45.096,131.654 -44.798,131.356 -44.133,131.356 v3@-43.627,130.85 ; C105.2@-43.492,130.062 C105.2@-43.449,130.105
  Top Signal w0.762: JP1.1@-55.677,121.336 -55.677,125.683 -54.693,126.667 R7.2@-53.074,126.667 ; R7.2@-52.993,126.718 -52.993,127.566 -52.615,127.944 -48.843,127.944 -48.388,128.399 R100.2@-48.388,130.189 -48.388,130.759 v3@-48.026,131.121 ; v3@-43.664,130.884 -43.664,130.319 C105.2@-43.449,130.105 ; C105.2@-43.492,130.062 U3.1@-41.39,130.062
  GND w0.762: v3(-48.03,131.103) -48.03,131.347 -47.206,132.171 -44.492,132.171 -43.672,131.351 v3(-43.672,130.943)
+5V0_XDS110: C100.1 JP1.2 JP2.1 R62.1 U101.4 U101.6 | length 67.2
  Top Signal w0.3: v1(-6.791,135.394) -6.791,135.993 R62.1@-6.679,136.105
  Top Signal w0.5: C100.1@-55.659,112.79 -55.575,112.874 v3(-54.825,112.874) ; U101.6@-53.935,111.574 -54.532,111.574 -54.825,111.867 v3(-54.825,112.874) ; U101.4@-53.935,112.874 v3(-54.825,112.874)
  Top Signal w0.762: C100.1@-55.677,112.846 JP1.2@-55.677,116.386
  PWR w1: -46.596,109.869 JP2.1@-44.705,109.869 -44.705,112.338
  Bottom Signal w0.3: JP2.1@-44.676,110.123 -44.676,112.285 -41.603,115.358 -35.392,115.358 -31.372,119.378 -23.512,119.378 -19.166,123.724 -10.151,123.724 -6.791,127.084 v1(-6.791,135.394) ; JP2.1@-44.462,110.259 JP2.1@-44.167,110.259
  other v3: -54.678,111.721
ADCINA0/B15/C15/DACA_OUT: J5/J7.70 R12.1 | length 4
  Top Signal w0.127: J5/J7.70@-49.531,15.889 R12.1@-45.49,15.889
ADCINA1/B7/D11/DACB_OUT: J1/J3.30 R13.1 | length 5.3
  Top Signal w0.127: J1/J3.30@-49.531,79.389 -47.905,77.763 -47.905,76.646 -46.958,75.698 R13.1@-46.402,75.698
ADCINA4/B8: J5/J7.66 R16.1 | length 4
  Top Signal w0.127: J5/J7.66@-49.531,26.049 R16.1@-45.49,26.049
ADCINA5: J5/J7.65 R17.1 | length 4.2
  Top Signal w0.127: J5/J7.65@-49.435,28.493 J5/J7.65@-49.531,28.589 R17.1@-45.49,28.589
ADCINA6/D14/E14: J1/J3.23 R18.1 | length 4.3
  Top Signal w0.127: J1/J3.23@-49.446,97.084 R18.1@-45.355,97.084
  Top Signal w0.203: J1/J3.23@-49.531,97.169 J1/J3.23@-49.446,97.084 ; R18.1@-45.355,97.084 R18.1@-45.27,96.999
ADCINA7/B30/C3/D12/E30: J1/J3.6 R19.1 | length 7.5
  Bottom Signal w0.254: J1/J3.6@-52.071,89.549 -50.873,90.747 -48.686,90.747 -47.488,89.549 R19.1@-45.554,89.549
ADCINA9: J5/J7.46 R20.1 | length 7.1
  Bottom Signal w0.127: J5/J7.46@-52.071,26.049 -50.776,27.344 R20.1@-45.49,27.344
ADCINA10/B1/C10: J5/J7.64 R21.1 | length 4
  Top Signal w0.127: J5/J7.64@-49.531,31.129 R21.1@-45.49,31.129
ADCINA11/B10/C0/PGA2_OUT: J1/J3.25 R22.1 | length 4.9
  Top Signal w0.127: J1/J3.25@-49.531,92.089 -48.011,92.089 -46.471,90.549 R22.1@-45.371,90.549 R22.1@-45.421,90.6
  Top Signal w0.254: J1/J3.25@-49.531,92.089 J1/J3.25@-49.48,92.039
ADCINA12/C5: J5/J7.69 R23.1 | length 4
  Top Signal w0.127: J5/J7.69@-49.531,18.429 R23.1@-45.49,18.429
ADCINA14/B14/C4/PGA1_OUT: J1/J3.26 R24.1 | length 9.4
  Top Signal w0.127: J1/J3.26@-49.531,89.549 -50.768,90.786 -50.768,92.605 -50.088,93.285 -48.288,93.285 -48.041,93.039 R24.1@-45.337,93.039
ADCINB0/C11: J5/J7.63 R109.1 | length 4
  Top Signal w0.15: J5/J7.63@-49.531,33.669 R109.1@-45.49,33.669
ADCINB2/C6/E12: J1/J3.24 R25.1 | length 4.3
  Top Signal w0.127: J1/J3.24@-49.523,94.637 R25.1@-45.272,94.637
  Top Signal w0.254: J1/J3.24@-49.531,94.629 J1/J3.24@-49.523,94.637 ; R25.1@-45.272,94.637 R25.1@-45.264,94.645
ADCINB4/C8: J5/J7.67 R27.1 | length 4
  Top Signal w0.127: J5/J7.67@-49.531,23.509 R27.1@-45.49,23.509
ADCINB5/D15/E15/PGA3_OUT: J5/J7.68 R84.1 | length 4
  Top Signal w0.127: J5/J7.68@-49.531,20.969 R84.1@-45.49,20.969
ADCINC14: J5/J7.42 R110.1 | length 10.8
  Bottom Signal w0.15: J5/J7.42@-52.071,36.209 -50.852,34.99 -43.616,34.99 R110.1@-42.302,36.304
ADCINPGA1_IN_N: R15.1 U17.6 | length 2.1
  Bottom Signal w0.15: R15.1@-43.765,82.705 R15.1@-43.974,82.915 -43.974,82.815 -43.531,82.371 U17.6@-43.531,81.263
ADCINPGA1_IN_P: R14.1 U17.4 | length 1.8
  Bottom Signal w0.15: R14.1@-45.206,82.915 -45.206,82.815 -44.831,82.439 U17.4@-44.831,81.263
ADCINPGA2_IN_N: R86.1 U17.9 | length 1.5
  Bottom Signal w0.15: U17.9@-41.581,81.263 R86.1@-41.581,82.689 ; R86.1@-41.581,82.816 R86.1@-41.512,82.885
ADCINPGA2_IN_P: R26.1 U17.7 | length 1.7
  Bottom Signal w0.15: U17.7@-42.881,81.263 R26.1@-42.881,82.635 ; R26.1@-42.881,82.762 R26.1@-42.734,82.908 R26.1@-42.734,82.808
ADCINPGA3_IN_N: R85.1 U17.12 | length 1.8
  Bottom Signal w0.15: U17.12@-39.631,81.263 -39.631,81.788 -39.282,82.136 -39.282,82.624 R85.1@-39.057,82.849
ADCINPGA3_IN_P: R87.1 U17.10 | length 2.1
  Bottom Signal w0.15: U17.10@-40.781,81.413 U17.10@-40.931,81.263 -40.931,82.143 -40.289,82.785 R87.1@-40.289,82.885
DEBUG_ID4: R58.1 U2.63 | length 4.5
  Top Signal w0.127: U2.63@-9.436,120.584 -9.436,116.966 -8.922,116.452 R58.1@-8.747,116.452
DEBUG_ID5: R59.1 U2.62 | length 6.2
  Top Signal w0.127: U2.62@-9.836,120.584 -9.836,115.633 -9.385,115.182 R59.1@-8.747,115.182
DEBUG_ID6: R60.1 U2.61 | length 7.7
  Top Signal w0.127: U2.61@-10.236,120.584 -10.236,114.725 -9.423,113.912 R60.1@-8.747,113.912
DEBUG_ID7: R61.1 U2.60 | length 9.2
  Top Signal w0.127: U2.60@-10.636,120.584 -10.636,113.737 -9.541,112.642 R61.1@-8.747,112.642
EQEP1A: C68.1 J12.1 R72.1 U13.21 | length 14.2
  Top Signal w0.2: U13.21@-27.669,11.702 -27.669,10.626 -26.936,9.893 -22.646,9.893 -21.591,8.838 J12.1@-21.591,2.554
EQEP1B: C69.1 J12.2 R73.1 U13.20 | length 12.4
  Top Signal w0.2: U13.20@-28.319,11.702 -28.319,10.335 -27.399,9.415 -24.807,9.415 -24.131,8.739 J12.2@-24.131,2.554
EQEP1I: C70.1 J12.3 R74.1 U13.19 | length 10.1
  Top Signal w0.2: U13.19@-28.969,11.702 -28.969,10.044 -27.035,8.11 -27.035,4.562 -26.671,4.198 J12.3@-26.671,2.554
EQEP3A: C71.1 J13.1 R75.1 U13.18 | length 15.1
  Top Signal w0.2: J13.1@-36.831,2.554 -36.831,8.464 -36.074,9.221 -30.984,9.221 -29.619,10.586 U13.18@-29.619,11.702
EQEP3B: C72.1 J13.2 R76.1 U13.17 | length 17.7
  Top Signal w0.2: J13.2@-39.133,2.467 -39.576,2.91 -39.576,8.999 -38.708,9.867 -31.135,9.867 -30.269,10.733 U13.17@-30.269,11.702
EQEP3I: C73.1 J13.3 R77.1 U13.16 | length 19.9
  Top Signal w0.2: J13.3@-41.911,2.554 -41.911,4.701 -42.378,5.168 -42.378,9.397 -41.348,10.427 -31.352,10.427 -30.919,10.86 U13.16@-30.919,11.702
